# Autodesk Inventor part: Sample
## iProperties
Created: 2008-04
Part Number: Sample
Document SubType Name: Modeling
Density: 1.06 g/cm^3
Material: ABS Plastic
Mass: 7.86799 g
Surface Area: 34.1494 cm^2
Volume: 7.42263 cm^3
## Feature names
1. Extrusion1
2. Extrusion2
3. Extrusion3
4. Rectangular Pattern2
